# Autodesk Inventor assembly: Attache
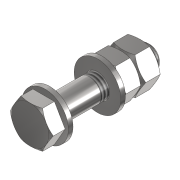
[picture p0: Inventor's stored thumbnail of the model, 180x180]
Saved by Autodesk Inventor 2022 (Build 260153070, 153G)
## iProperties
Created: 2021-07
Part Number: Attache
Document SubType Name: Assembly
Designer: Fabian
Author: Fabian
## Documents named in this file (4)
- C:\Users\Fabian\Google Drive\01_Giup\01_Clients\07_ENI\Manuscrit\Fichiers_exercice\Chapitre_06\Exercice_reseau\Attache.iam
- C:\Users\Fabian\Google Drive\01_Giup\01_Clients\07_ENI\Manuscrit\Fichiers_exercice\CC\fr-FR\ISO 7089\ISO 7089 - 10 - 140 HV(1).ipt
- C:\Users\Fabian\Google Drive\01_Giup\01_Clients\07_ENI\Manuscrit\Fichiers_exercice\CC\fr-FR\ISO 4014(2)\ISO 4014 - M10 x 45 - ISO.ipt
- C:\Users\Fabian\Google Drive\01_Giup\01_Clients\07_ENI\Manuscrit\Fichiers_exercice\CC\fr-FR\ISO 4032(2)\ISO 4032 - M10 - ISO.ipt
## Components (5 placed, 3 different names)
1. ISO 7089 10:1
2. ISO 4014 M10 x 45:1
3. ISO 7089 10:2
4. ISO 4032 M10:1
5. ISO 4032 M10:2
## Named parameters: d0_d9 = 0, d1_d10 = 0
